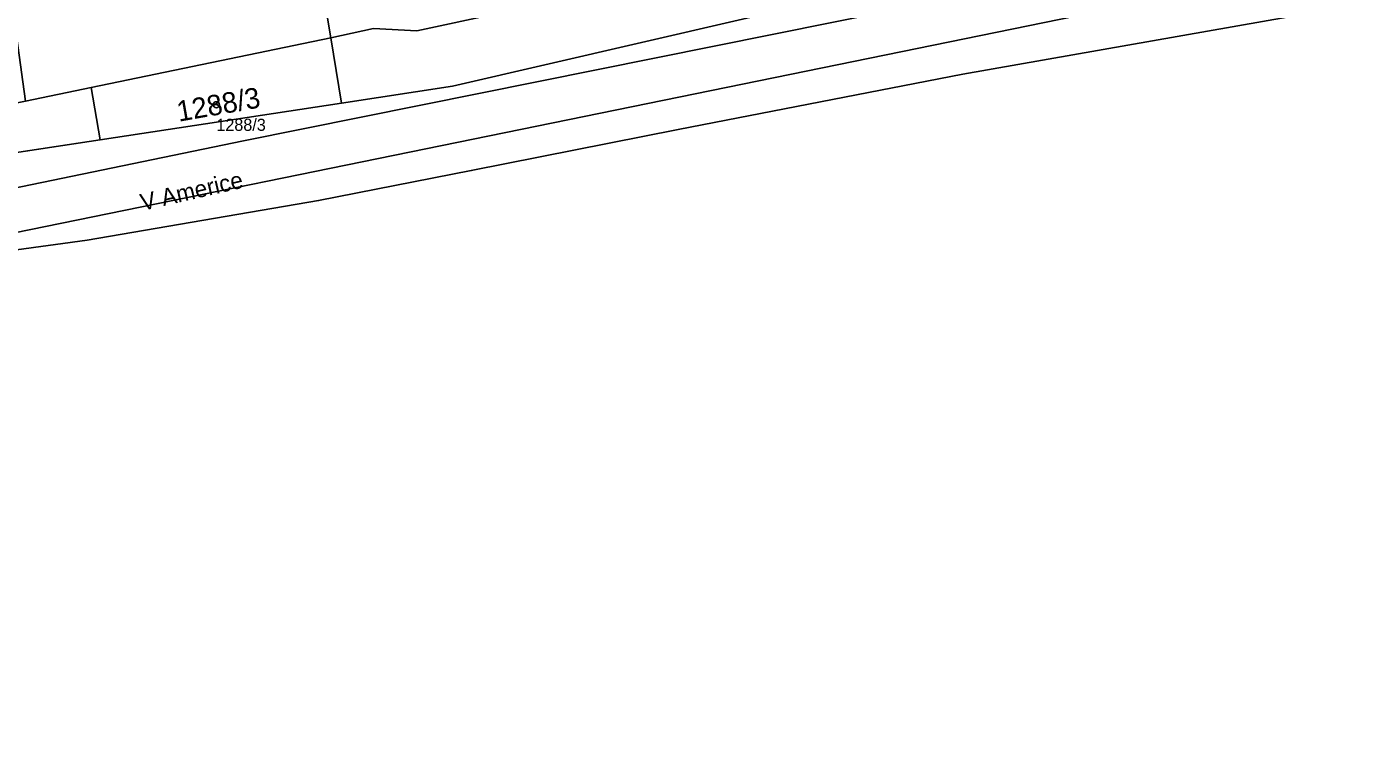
# Model space of a CAD drawing. Extents: x -754731 to -751381, y -1060564 to -1058101.
# Drawn here: x -753246.6 to -753136.1, y -1059255.6 to -1059196.6 of the extents above; entities that cross this region are included whole.
import ezdxf

# ---------------------------------------------------------------- set-up
doc = ezdxf.new("R2010")
doc.units = 0
for name, color, linetype in [('Definiční body', 7, 'Continuous'), ('Hranice parcel', 7, 'Continuous'), ('Parcelní čísla', 7, 'Continuous'), ('Polygon parcely', 7, 'Continuous'), ('Pop  PČ popisy', 7, 'Continuous')]:
    doc.layers.add(name, color=color, linetype=linetype)

msp = doc.modelspace()

# ---------------------------------------------------------------- linework, layer by layer
at = {"layer": 'Definiční body'}
msp.add_circle((-753230.96, -1059203.09), 0.25, dxfattribs=at)
at = {"layer": 'Hranice parcel'}
for p, q in [((-753241.32, -1059201.67), (-753221.49, -1059197.55)), ((-753220.6, -1059202.95), (-753221.49, -1059197.55)), ((-753246.75, -1059202.8), (-753241.32, -1059201.67)), ((-753240.58, -1059205.99), (-753241.32, -1059201.67)), ((-753240.58, -1059205.99), (-753220.6, -1059202.95)), ((-753265.65, -1059209.81), (-753240.58, -1059205.99))]:
    msp.add_line(p, q, dxfattribs=at)
for points in [[(-753318.4, -1059239.83), (-753315.16, -1059232.94), (-753306.77, -1059225.16), (-753296.24, -1059220.04), (-753228.71, -1059206.08), (-753160.61, -1059192.33), (-753099.5, -1059178.14), (-752969.12, -1059140.59), (-752910.4, -1059123.52), (-752902.66, -1059122.53)], [(-752901.08, -1059134.56), (-752930.29, -1059142.42), (-753047.61, -1059176.32), (-753077.08, -1059182.17), (-753105.8, -1059191.92), (-753139.89, -1059195.41), (-753169.22, -1059200.55), (-753192.78, -1059205.14), (-753209.88, -1059208.54), (-753222.5, -1059211.02), (-753241.63, -1059214.29), (-753253.97, -1059215.99), (-753263.52, -1059219.25), (-753280.81, -1059222.69), (-753290.55, -1059226.23), (-753297.85, -1059228.84), (-753311.9, -1059239.4), (-753313.73, -1059252.26), (-753310.19, -1059261.66)], [(-752967.76, -1059145.34), (-753098.67, -1059182.14), (-753159.92, -1059195.77), (-753294.94, -1059223.34), (-753313.2, -1059234.53), (-753317.94, -1059244.71), (-753319.43, -1059256.65), (-753315.13, -1059273.65)], [(-753221.49, -1059197.55), (-753223.05, -1059188.23), (-753229.47, -1059149.91)], [(-753220.6, -1059202.95), (-753211.44, -1059201.56), (-753156.91, -1059188.92)], [(-753221.49, -1059197.55), (-753217.95, -1059196.78), (-753214.37, -1059196.97), (-753200.75, -1059194.02)]]:
    msp.add_lwpolyline(points, dxfattribs=at)
at = {"layer": 'Polygon parcely'}
for points in [[(-752969.12, -1059140.59), (-753099.5, -1059178.14), (-753160.61, -1059192.33), (-753228.71, -1059206.08), (-753296.24, -1059220.04), (-753306.77, -1059225.16), (-753315.16, -1059232.94), (-753318.4, -1059239.83), (-753320.52, -1059244.36), (-753321.9, -1059257.12), (-753319.94, -1059264.17), (-753317.1, -1059274.45), (-753313.77, -1059282.49), (-753313.17, -1059283.94), (-753312.1, -1059279.77), (-753315.13, -1059273.65), (-753319.43, -1059256.65), (-753317.94, -1059244.71), (-753313.2, -1059234.53), (-753294.94, -1059223.34), (-753159.92, -1059195.77), (-753098.67, -1059182.14), (-752967.76, -1059145.34)], [(-752999.15, -1059144.11), (-753043.42, -1059157.26), (-753059.68, -1059164.72), (-753097.9, -1059174.44), (-753156.91, -1059188.92), (-753211.44, -1059201.56), (-753220.6, -1059202.95), (-753240.58, -1059205.99), (-753265.65, -1059209.81), (-753296.1, -1059217.08), (-753310.31, -1059218.28), (-753312.87, -1059223.47), (-753314.33, -1059225.94), (-753316.33, -1059230.89), (-753318.4, -1059239.83), (-753315.16, -1059232.94), (-753306.77, -1059225.16), (-753296.24, -1059220.04), (-753228.71, -1059206.08), (-753160.61, -1059192.33), (-753099.5, -1059178.14), (-752969.12, -1059140.59)], [(-753310.19, -1059261.66), (-753313.73, -1059252.26), (-753311.9, -1059239.4), (-753297.85, -1059228.84), (-753290.55, -1059226.23), (-753280.81, -1059222.69), (-753263.52, -1059219.25), (-753253.97, -1059215.99), (-753241.63, -1059214.29), (-753222.5, -1059211.02), (-753209.88, -1059208.54), (-753192.78, -1059205.14), (-753169.22, -1059200.55), (-753139.89, -1059195.41), (-753105.8, -1059191.92), (-753077.08, -1059182.17), (-753047.61, -1059176.32), (-752930.29, -1059142.42)], [(-752930.29, -1059142.42), (-753047.61, -1059176.32), (-753077.08, -1059182.17), (-753105.8, -1059191.92), (-753139.89, -1059195.41), (-753169.22, -1059200.55), (-753192.78, -1059205.14), (-753209.88, -1059208.54), (-753222.5, -1059211.02), (-753241.63, -1059214.29), (-753253.97, -1059215.99), (-753263.52, -1059219.25), (-753280.81, -1059222.69), (-753290.55, -1059226.23), (-753297.85, -1059228.84), (-753311.9, -1059239.4), (-753313.73, -1059252.26), (-753310.19, -1059261.66), (-753308.35, -1059277.98), (-753167.3, -1059267.13), (-753137.58, -1059262.6), (-753027.97, -1059233.36), (-753008.69, -1059226.52)], [(-752967.76, -1059145.34), (-753098.67, -1059182.14), (-753159.92, -1059195.77), (-753294.94, -1059223.34), (-753313.2, -1059234.53), (-753317.94, -1059244.71), (-753319.43, -1059256.65)]]:
    msp.add_lwpolyline(points, dxfattribs=at)
for points in [[(-753217.95, -1059196.78), (-753214.37, -1059196.97), (-753200.75, -1059194.02), (-753208.64, -1059143.94), (-753229.47, -1059149.91), (-753223.05, -1059188.23), (-753221.49, -1059197.55)], [(-753229.94, -1059150.05), (-753228.98, -1059152.94), (-753234.29, -1059154.72), (-753235.31, -1059151.66), (-753236.77, -1059152.1), (-753236.22, -1059154.45), (-753252.79, -1059159.1), (-753246.75, -1059202.8), (-753241.32, -1059201.67), (-753221.49, -1059197.55), (-753223.05, -1059188.23), (-753229.47, -1059149.91)], [(-753211.44, -1059201.56), (-753156.91, -1059188.92), (-753157.48, -1059184.79), (-753159.4, -1059185.05), (-753180.1, -1059189.54), (-753200.75, -1059194.02), (-753214.37, -1059196.97), (-753217.95, -1059196.78), (-753221.49, -1059197.55), (-753220.6, -1059202.95)], [(-753221.49, -1059197.55), (-753241.32, -1059201.67), (-753240.58, -1059205.99), (-753220.6, -1059202.95)], [(-753265.65, -1059209.81), (-753240.58, -1059205.99), (-753241.32, -1059201.67), (-753246.75, -1059202.8), (-753248.22, -1059203.11), (-753266.06, -1059207.04)]]:
    msp.add_lwpolyline(points, close=True, dxfattribs=at)

# ---------------------------------------------------------------- texts
at = {"layer": 'Definiční body'}
msp.add_text('1288/3', height=1, dxfattribs=at).set_placement((-753230.96, -1059205.25))
at = {"layer": 'Parcelní čísla'}
msp.add_text('1288/3', height=1.7, rotation=10, dxfattribs=at).set_placement((-753234.07, -1059204.5))
at = {"layer": 'Pop  PČ popisy'}
msp.add_text('V Americe', height=1.4, rotation=13, dxfattribs=at).set_placement((-753237.06, -1059211.88))

doc.saveas('drawing.dxf')
